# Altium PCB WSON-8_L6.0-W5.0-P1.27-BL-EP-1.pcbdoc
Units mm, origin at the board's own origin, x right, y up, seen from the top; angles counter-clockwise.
Board outline 18.14 x 20.23 mm, 2 copper layers (Top Layer, Bottom Layer), stack 0 mm thick; 1 components, 0 nets, 9 pads, 0 vias.
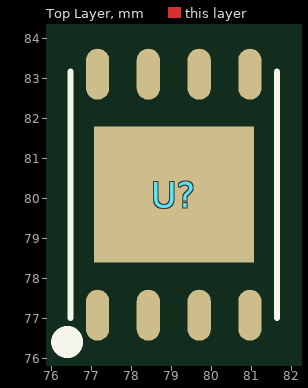
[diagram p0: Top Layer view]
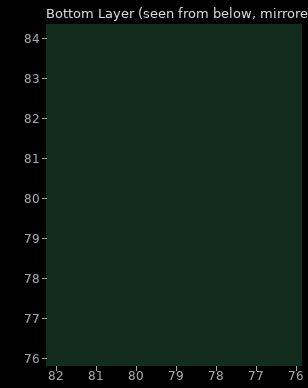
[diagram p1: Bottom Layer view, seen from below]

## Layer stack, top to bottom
Top Layer: signal copper (thickness not stored)
Bottom Layer: signal copper (thickness not stored)

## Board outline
87.993,69.85 69.85,69.85 69.85,90.083 87.993,90.083

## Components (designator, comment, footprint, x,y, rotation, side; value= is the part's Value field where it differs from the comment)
U? "" WSON-8_L6.0-W5.0-P1.27-BL-EP-1 79.067,80.083 r0 top

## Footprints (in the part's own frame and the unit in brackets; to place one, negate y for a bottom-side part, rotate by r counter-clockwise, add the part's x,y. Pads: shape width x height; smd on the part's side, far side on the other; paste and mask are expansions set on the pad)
WSON-8_L6.0-W5.0-P1.27-BL-EP-1 [mm]
  oval 0.581x1.276 smd paste+0 mask+0.05: 1(-1.905,-3.013) 2(-0.635,-3.013) 3(0.635,-3.013) 4(1.905,-3.013) 5(1.905,3.013) 6(0.635,3.013) 7(-0.635,3.013) 8(-1.905,3.013)
  rect 4x3.4 smd paste+0 mask+0.05: 9(0,0)
  silkscreen extent -2.87,-3.88 2.58,3.08

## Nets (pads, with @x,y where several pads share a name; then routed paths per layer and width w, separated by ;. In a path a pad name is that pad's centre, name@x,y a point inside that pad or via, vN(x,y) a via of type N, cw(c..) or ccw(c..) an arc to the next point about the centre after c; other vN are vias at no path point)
pads on no net: U?.1 U?.2 U?.3 U?.4 U?.5 U?.6 U?.7 U?.8 U?.9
